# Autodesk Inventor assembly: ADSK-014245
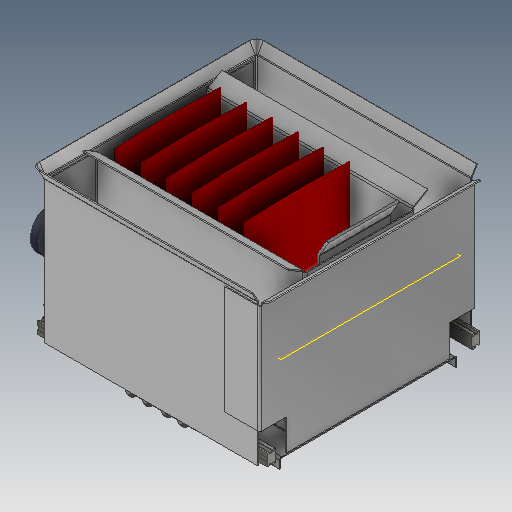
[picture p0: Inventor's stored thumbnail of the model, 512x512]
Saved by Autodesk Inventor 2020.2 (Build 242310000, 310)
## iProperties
RuleStatus: InUse
Shininess: 0.0
Length Units: 11269
Angle Units: 11279
Time Units: 11290
Mass Units: 11283
Length Display Precision: 3
Angle Display Precision: 2
Compacted: True
Created: 2000-01
Part Number: ADSK-014245
Document SubType Name: Assembly
Designer: glanglot
Mass: 8116.9 g
Surface Area: 15485.2 cm^2
Volume: 2060.68 cm^3
Density: 3.93894 g/cm^3
Density: 0.0
Volumn: 0.0
Area: 0.0
PropertySet Name: Model Information
Control State: 0
Checked Out: False
Master: False
Dimensions: 342,2x241,9x339,5 mm
Mass: 8,117 kg
DocNumber: ADSK-014245
Folder: 01 - Themengebiete\Simplification\01 - Packaging machine\
Original: C:\AB_Vault\CAD\01 - Themengebiete\Simplification\01 - Packaging machine\500406.iam
VDS_Category: 3D Komponenten
VDS_NumSchm: Autodesk
Author: glanglot
Revision Number: -
Title: box
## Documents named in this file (14)
- D:\07 - DEMODATEN\OTX 2019 - Dataset - UPDATE - Dez2019\Designs\07-Packing machine\ADSK-014245.iam
- D:\07 - DEMODATEN\OTX 2019 - Dataset - UPDATE - Dez2019\Designs\07-Packing machine\Parts\ADSK-011378.ipt
- D:\07 - DEMODATEN\OTX 2019 - Dataset - UPDATE - Dez2019\Designs\07-Packing machine\500409.iam
- D:\07 - DEMODATEN\OTX 2019 - Dataset - UPDATE - Dez2019\Designs\07-Packing machine\17oz pouch pack pattern.iam
- D:\07 - DEMODATEN\OTX 2019 - Dataset - UPDATE - Dez2019\Designs\07-Packing machine\A105193.iam
- D:\07 - DEMODATEN\OTX 2019 - Dataset - UPDATE - Dez2019\Designs\07-Packing machine\500430.iam
- D:\07 - DEMODATEN\OTX 2019 - Dataset - UPDATE - Dez2019\Designs\07-Packing machine\Parts\ADSK-011396.ipt
- D:\07 - DEMODATEN\OTX 2019 - Dataset - UPDATE - Dez2019\Designs\07-Packing machine\Parts\ADSK-011810.ipt
- D:\07 - DEMODATEN\OTX 2019 - Dataset - UPDATE - Dez2019\Designs\07-Packing machine\A105192.iam
- D:\07 - DEMODATEN\OTX 2019 - Dataset - UPDATE - Dez2019\Designs\07-Packing machine\500445.iam
- D:\07 - DEMODATEN\OTX 2019 - Dataset - UPDATE - Dez2019\Designs\07-Packing machine\500447.iam
- D:\07 - DEMODATEN\OTX 2019 - Dataset - UPDATE - Dez2019\Designs\07-Packing machine\500550.iam
- D:\07 - DEMODATEN\OTX 2019 - Dataset - UPDATE - Dez2019\Designs\07-Packing machine\ADSK-014246.iam
- D:\07 - DEMODATEN\OTX 2019 - Dataset - UPDATE - Dez2019\Content Center Files\de-DE\ISO 4762(2)\ISO 4762 - M4 x 16ISO.ipt
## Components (26 placed, 13 different names)
1. ADSK-014246:1 [sub-assembly] — Mate:2, Flush:3, Mate:4, Flush:4, Mate:6, Mate:7, Mate:8, Flush:8, Mate:10, Flush:10, Flush:11, Flush:12, Passend:21, Passend:22, Passend:27, Passend:28, Passend:29, Fluchtend:17, Fluchtend:21
2. ADSK-011378:1 — Passend:24, Passend:25, Passend:26
3. 500409:1 [sub-assembly] — Insert:3, Insert:4, Passend:19, Passend:20, Passend:23, Passend:25, Passend:26
4. 17oz pouch pack pattern:1 [sub-assembly] — Passend:40, PRODUCT, Fluchtend:21
5. A105193:1 [sub-assembly] — Mate:2, Flush:3, Passend:19, Passend:20, Passend:22, Passend:23
6. A105193:2 [sub-assembly] — Mate:4, Flush:4, Passend:21
7. 500430:1 [sub-assembly] — Passend:27, Passend:28, Passend:29, Passend:30, Passend:31, Passend:32, Passend:33
8. ADSK-011396:1 — Insert:3, Insert:4, Passend:24
9. A105192:1 [sub-assembly] — Flush:13, Mate:13, Passend:38
10. ADSK-011810:1 — Mate:6, Flush:7, Flush:13, Mate:13, Flush:15, Mate:15, Fluchtend:17, Fluchtend:18
11. A105192:2 [sub-assembly] — Flush:14, Mate:14, Passend:36, Passend:37, STROKE_02
12. ADSK-011810:2 — Mate:7, Flush:7, Mate:8, Flush:14, Mate:14, Flush:16, Mate:17, Fluchtend:18, STROKE_01, STROKE_02
13. 500445:1 [sub-assembly] — Flush:8, Passend:36, Passend:37, Passend:38, PRODUCT
14. A105192:3 [sub-assembly] — Flush:15, Mate:15, Mate:16, Passend:34
15. A105192:4 [sub-assembly] — Flush:16, Mate:17, Mate:18, Passend:35, STROKE_01
16. 500447:1 [sub-assembly] — Mate:10, Mate:16, Mate:18, Passend:34, Passend:35
17. 500550:1 [sub-assembly] — Passend:31, Passend:32
18. 500550:2 [sub-assembly] — Passend:30, Passend:33
19. ISO 4762 M4 x 16:1
20. ISO 4762 M4 x 16:2
21. ISO 4762 M4 x 16:3
22. ISO 4762 M4 x 16:4
23. ISO 4762 M4 x 16:5
24. ISO 4762 M4 x 16:6
25. ISO 4762 M4 x 16:7
26. ISO 4762 M4 x 16:8
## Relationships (52: Mate 34, Flush 16, Insert 2)
- STROKE_01 [Flush]: ADSK-011810:2 ↔ A105192:4
- STROKE_02 [Mate]: A105192:2 ↔ ADSK-011810:2
- Mate:2: ADSK-014246:1 ↔ A105193:1
- Flush:3: ADSK-014246:1 ↔ A105193:1
- Mate:4: ADSK-014246:1 ↔ A105193:2
- Flush:4: ADSK-014246:1 ↔ A105193:2
- Insert:3: 500409:1 ↔ ADSK-011396:1
- Insert:4: 500409:1 ↔ ADSK-011396:1
- Mate:6: ADSK-014246:1 ↔ ADSK-011810:1
- Mate:7: ADSK-014246:1 ↔ ADSK-011810:2
- Flush:7: ADSK-011810:1 ↔ ADSK-011810:2
- Mate:8: ADSK-014246:1 ↔ ADSK-011810:2
- Flush:8: ADSK-014246:1 ↔ 500445:1
- Mate:10: ADSK-014246:1 ↔ 500447:1
- Flush:10: ADSK-014246:1
- Flush:11: ADSK-014246:1
- Flush:12: ADSK-014246:1
- Flush:13: A105192:1 ↔ ADSK-011810:1
- Mate:13: A105192:1 ↔ ADSK-011810:1
- Flush:14: A105192:2 ↔ ADSK-011810:2
- Mate:14: A105192:2 ↔ ADSK-011810:2
- Flush:15: ADSK-011810:1 ↔ A105192:3
- Mate:15: ADSK-011810:1 ↔ A105192:3
- Mate:16: A105192:3 ↔ 500447:1
- Flush:16: ADSK-011810:2 ↔ A105192:4
- Mate:17: ADSK-011810:2 ↔ A105192:4
- Mate:18: A105192:4 ↔ 500447:1
- Passend:19 [Mate]: 500409:1 ↔ A105193:1
- Passend:20 [Mate]: 500409:1 ↔ A105193:1
- Passend:21 [Mate]: ADSK-014246:1 ↔ A105193:2
- Passend:22 [Mate]: ADSK-014246:1 ↔ A105193:1
- Passend:23 [Mate]: 500409:1 ↔ A105193:1
- Passend:24 [Mate]: ADSK-011378:1 ↔ ADSK-011396:1
- Passend:25 [Mate]: ADSK-011378:1 ↔ 500409:1
- Passend:26 [Mate]: ADSK-011378:1 ↔ 500409:1
- Passend:27 [Mate]: ADSK-014246:1 ↔ 500430:1
- Passend:28 [Mate]: ADSK-014246:1 ↔ 500430:1
- Passend:29 [Mate]: ADSK-014246:1 ↔ 500430:1
- Passend:30 [Mate]: 500430:1 ↔ 500550:2
- Passend:31 [Mate]: 500430:1 ↔ 500550:1
- Passend:32 [Mate]: 500430:1 ↔ 500550:1
- Passend:33 [Mate]: 500430:1 ↔ 500550:2
- Passend:34 [Mate]: A105192:3 ↔ 500447:1
- Passend:35 [Mate]: A105192:4 ↔ 500447:1
- Passend:36 [Mate]: A105192:2 ↔ 500445:1
- Passend:37 [Mate]: A105192:2 ↔ 500445:1
- Fluchtend:17 [Flush]: ADSK-014246:1 ↔ ADSK-011810:1
- Fluchtend:18 [Flush]: ADSK-011810:1 ↔ ADSK-011810:2
- Passend:38 [Mate]: A105192:1 ↔ 500445:1
- Passend:40 [Mate]: 17oz pouch pack pattern:1
- PRODUCT [Flush]: 17oz pouch pack pattern:1 ↔ 500445:1
- Fluchtend:21 [Flush]: ADSK-014246:1 ↔ 17oz pouch pack pattern:1
## Named parameters: STROKE = 0.5 mm
